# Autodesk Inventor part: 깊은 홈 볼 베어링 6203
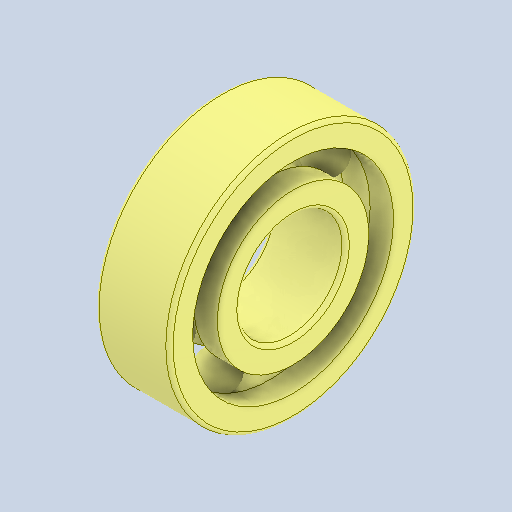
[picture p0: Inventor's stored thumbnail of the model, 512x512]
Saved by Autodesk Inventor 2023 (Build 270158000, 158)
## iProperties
Created: 2025-03
Part Number: 깊은 홈 볼 베어링 6203
Material: 강철, 연강
Description: 깊은 그루브 볼 베어링
Document SubType Name: Modeling
Designer: ADMIN_PC
Density: 7.85 g/cm^3
Appearance: 기본값
Author: jhkim
Sending System: Autodesk Inventor 2025
Preprocessor: ST-DEVELOPER v20
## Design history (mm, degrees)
feature "Solid1"
feature "Solid1:1"
feature "Solid1:2"
feature "Solid1:3"
feature "Solid1:4"
feature "Solid1:5"
feature "Solid1:6"
feature "Solid1:7"
feature "Solid1:8"
node "솔리드1"
node "솔리드2"
node "솔리드3"
node "솔리드4"
node "솔리드5"
node "솔리드6"
node "솔리드7"
node "솔리드8"
node "솔리드9"
